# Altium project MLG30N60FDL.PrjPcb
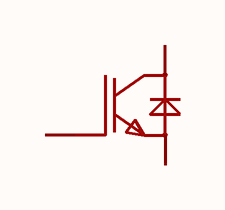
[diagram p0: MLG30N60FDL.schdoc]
1 sheet, 1 parts. Net scope: global (net labels, ports and power ports of the same name join across sheets).

## Sheet MLG30N60FDL.schdoc
size 127 x 101 mm

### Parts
Q?  mlg30n60fdl  [TO-247-3_L15.6-W4.7-P5.45-L]  (value not drawn)

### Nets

Not connected (* = marked no-connect by the designer): Q? 1(G) 2(C) 3(E)

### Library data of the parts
Q? = mlg30n60fdl: IGBT类型:FS(场截止)集射极击穿电压:600V集电极电流:60A耗散功率:187W; Manufacturer: minos(迈诺斯); AddInBom: yes; ModelId: c7ff900f52804e23982f5352ae914652; ModelTransform: 614.9594,185.078,0,0,0,0,0,14.252,-196.85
